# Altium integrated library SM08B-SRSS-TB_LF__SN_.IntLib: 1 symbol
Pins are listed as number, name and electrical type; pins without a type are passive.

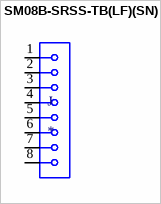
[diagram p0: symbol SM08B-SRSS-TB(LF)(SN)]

## SM08B-SRSS-TB(LF)(SN)
designator J
Connector Header Surface Mount, Right Angle 8 position 0.039 _1.00mm_; MF: JST Sales; MP: SM08B-SRSS-TB_LF__SN_
footprint JST_SM08B-SRSS-TB(LF)(SN)
pins: 1, 2, 3, 4, 5, 6, 7, 8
